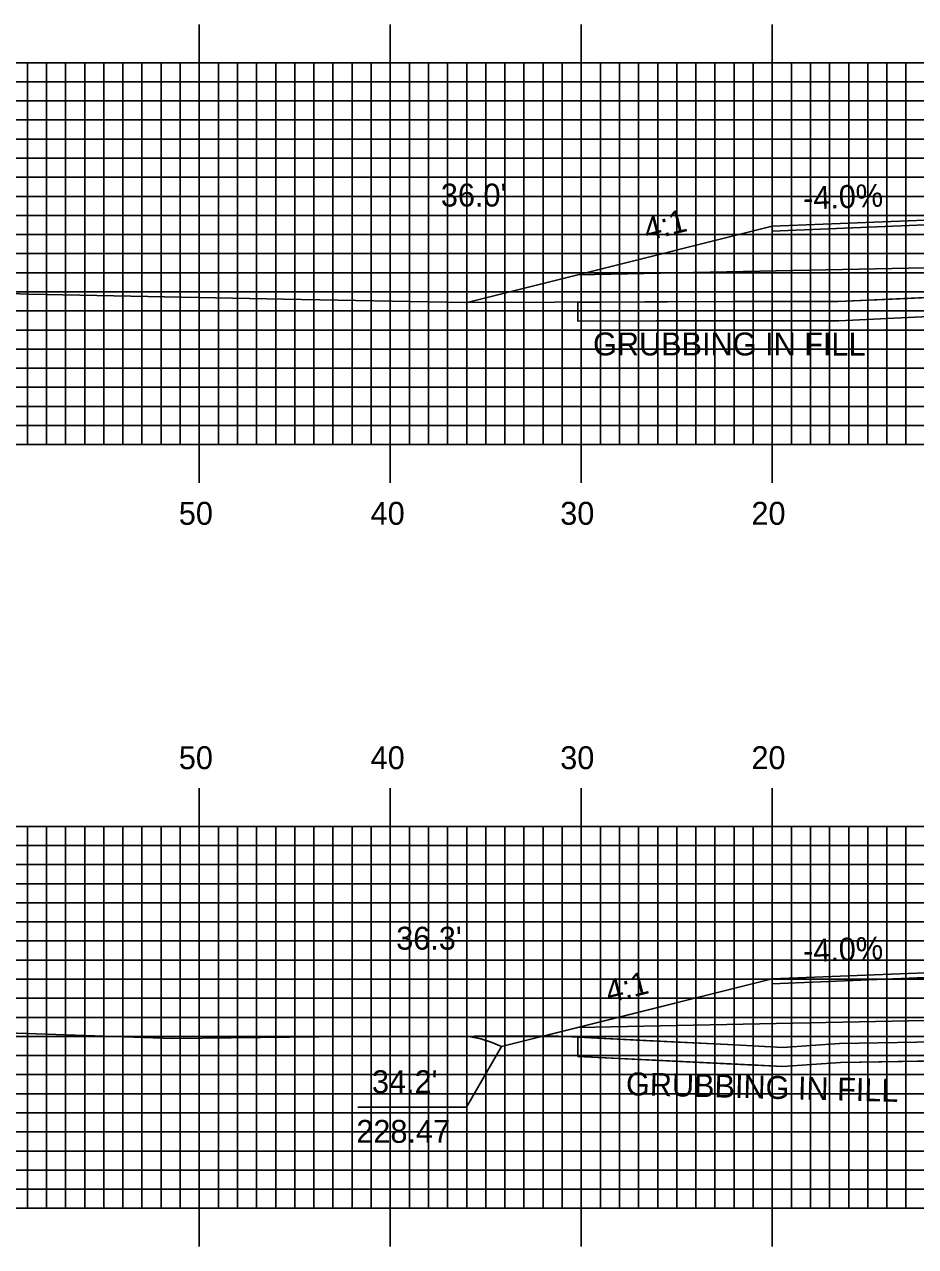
# Model space of a CAD drawing. Extents: x 1803503 to 1803847, y 442591 to 442811.
# Drawn here: x 1803610 to 1803656.6, y 442686.7 to 442750.7 of the extents above; entities that cross this region are included whole.
import ezdxf

# ---------------------------------------------------------------- set-up
doc = ezdxf.new("R2010")
doc.units = 0
for name, color, linetype in [('ANNOTATION', 7, 'Continuous'), ('D_Roadway_Centerline', 7, 'Continuous'), ('D_Roadway_Edge_Shoulder', 7, 'Continuous'), ('D_Roadway_SlopeLines', 7, 'Continuous'), ('D_Roadway_SubGrade', 7, 'Continuous'), ('D_Text_Standard', 7, 'Continuous'), ('GRUBBING IN FILL', 7, 'Continuous'), ('H_V ANNOTATION', 7, 'Continuous'), ('MAJOR', 7, 'Continuous'), ('MINOR', 7, 'Continuous'), ('S_Roadway_Centerline', 7, 'Continuous')]:
    doc.layers.add(name, color=color, linetype=linetype)

msp = doc.modelspace()

# ---------------------------------------------------------------- linework, layer by layer
at = {"layer": 'ANNOTATION'}
msp.add_lwpolyline([(1803627.447, 442693.968), (1803633.139, 442693.968), (1803634.967, 442697.135)], dxfattribs=at)
at = {"layer": 'D_Roadway_Centerline'}
for points in [[(1803633.162, 442736.104), (1803637.141, 442737.098), (1803638.967, 442737.555), (1803649.141, 442740.098), (1803657.141, 442740.418), (1803669.141, 442740.706), (1803681.141, 442740.994), (1803689.141, 442740.674), (1803699.315, 442738.131), (1803713.175, 442734.666)], [(1803632.797, 442697.673), (1803633.34, 442697.641), (1803633.882, 442697.541), (1803634.424, 442697.372), (1803634.967, 442697.135), (1803638.967, 442698.135), (1803649.141, 442700.678), (1803657.141, 442700.998), (1803669.141, 442701.286), (1803681.141, 442701.574), (1803689.141, 442701.254), (1803699.315, 442698.711), (1803706.969, 442696.797)]]:
    msp.add_lwpolyline(points, dxfattribs=at)
at = {"layer": 'D_Roadway_Edge_Shoulder'}
for points in [[(1803657.141, 442740.418), (1803649.141, 442740.098), (1803649.141, 442739.848), (1803657.141, 442740.168)], [(1803657.141, 442700.998), (1803649.141, 442700.678), (1803649.141, 442700.428), (1803657.141, 442700.748)]]:
    msp.add_lwpolyline(points, close=True, dxfattribs=at)
at = {"layer": 'D_Roadway_SlopeLines'}
for points in [[(1803649.141, 442740.098), (1803638.967, 442737.555), (1803637.141, 442737.098), (1803633.162, 442736.104)], [(1803649.141, 442700.678), (1803634.967, 442697.135)], [(1803634.967, 442697.135), (1803634.424, 442697.372), (1803633.882, 442697.541), (1803633.34, 442697.641), (1803632.797, 442697.673)]]:
    msp.add_lwpolyline(points, dxfattribs=at)
at = {"layer": 'D_Roadway_SubGrade'}
for points in [[(1803657.141, 442737.918), (1803638.967, 442737.555), (1803649.141, 442740.098), (1803649.141, 442739.848), (1803657.141, 442740.168), (1803669.141, 442740.456), (1803681.141, 442740.744), (1803689.141, 442740.424), (1803689.141, 442740.674), (1803699.315, 442738.131), (1803681.141, 442738.494), (1803669.141, 442738.206)], [(1803657.141, 442698.498), (1803638.967, 442698.135), (1803649.141, 442700.678), (1803649.141, 442700.428), (1803657.141, 442700.748), (1803669.141, 442701.036), (1803681.141, 442701.324), (1803689.141, 442701.004), (1803689.141, 442701.254), (1803699.315, 442698.711), (1803681.141, 442699.074), (1803669.141, 442698.786)]]:
    msp.add_lwpolyline(points, close=True, dxfattribs=at)
at = {"layer": 'GRUBBING IN FILL'}
for p, q in [((1803638.967, 442736.125), (1803638.967, 442735.125)), ((1803638.967, 442736.125), (1803638.967, 442735.125)), ((1803638.967, 442697.625), (1803638.967, 442696.624)), ((1803638.967, 442697.625), (1803638.967, 442696.624))]:
    msp.add_line(p, q, dxfattribs=at)
for points in [[(1803638.967, 442736.125), (1803640.1, 442736.129), (1803647.171, 442736.154), (1803649.883, 442736.153), (1803652.596, 442736.152), (1803656.22, 442736.322), (1803659.844, 442736.493), (1803662, 442736.585), (1803664.222, 442736.368), (1803667.485, 442736.044), (1803668.526, 442735.936), (1803669.141, 442735.915), (1803669.141, 442734.915), (1803668.457, 442734.938), (1803667.401, 442735.047), (1803664.176, 442735.368), (1803662.007, 442735.579), (1803659.886, 442735.494), (1803656.253, 442735.323), (1803652.62, 442735.152), (1803649.896, 442735.153), (1803647.172, 442735.154), (1803643.069, 442735.139), (1803638.967, 442735.125)], [(1803638.967, 442736.125), (1803640.1, 442736.129), (1803647.171, 442736.154), (1803649.883, 442736.153), (1803652.596, 442736.152), (1803656.22, 442736.322), (1803659.844, 442736.493), (1803662, 442736.585), (1803664.222, 442736.368), (1803667.485, 442736.044), (1803668.526, 442735.936), (1803669.141, 442735.915), (1803669.141, 442734.915), (1803668.457, 442734.938), (1803667.401, 442735.047), (1803664.176, 442735.368), (1803662.007, 442735.579), (1803659.886, 442735.494), (1803656.253, 442735.323), (1803652.62, 442735.152), (1803649.896, 442735.153), (1803647.172, 442735.154), (1803643.069, 442735.139), (1803638.967, 442735.125)], [(1803638.967, 442697.625), (1803642.38, 442697.456), (1803647.158, 442697.219), (1803648.422, 442697.153), (1803649.687, 442697.087), (1803651.177, 442697.19), (1803652.667, 442697.293), (1803659.74, 442697.415), (1803666.814, 442697.536), (1803669.141, 442697.425), (1803669.141, 442696.424), (1803666.798, 442696.536), (1803659.754, 442696.415), (1803652.71, 442696.294), (1803651.203, 442696.189), (1803649.695, 442696.085), (1803648.401, 442696.153), (1803643.037, 442696.422), (1803638.967, 442696.624)], [(1803638.967, 442697.625), (1803642.38, 442697.456), (1803647.158, 442697.219), (1803648.422, 442697.153), (1803649.687, 442697.087), (1803651.177, 442697.19), (1803652.667, 442697.293), (1803659.74, 442697.415), (1803666.814, 442697.536), (1803669.141, 442697.425), (1803669.141, 442696.424), (1803666.798, 442696.536), (1803659.754, 442696.415), (1803652.71, 442696.294), (1803651.203, 442696.189), (1803649.695, 442696.085), (1803648.401, 442696.153), (1803643.037, 442696.422), (1803638.967, 442696.624)]]:
    msp.add_lwpolyline(points, close=True, dxfattribs=at)
for points in [[(1803638.967, 442735.125), (1803647.172, 442735.154), (1803652.62, 442735.152), (1803659.886, 442735.494), (1803661.922, 442735.57), (1803662.007, 442735.579), (1803666.345, 442735.157), (1803668.457, 442734.938), (1803669.539, 442734.901), (1803680.472, 442734.876), (1803689.308, 442734.416), (1803694.454, 442734.291), (1803699.315, 442734.13)], [(1803638.967, 442735.125), (1803647.172, 442735.154), (1803652.62, 442735.152), (1803659.886, 442735.494), (1803661.922, 442735.57), (1803662.007, 442735.579), (1803666.345, 442735.157), (1803668.457, 442734.938), (1803669.539, 442734.901), (1803680.472, 442734.876), (1803689.308, 442734.416), (1803694.454, 442734.291), (1803699.315, 442734.13)], [(1803638.967, 442696.624), (1803647.107, 442696.22), (1803649.695, 442696.085), (1803652.71, 442696.294), (1803666.798, 442696.536), (1803670.752, 442696.347), (1803672.896, 442696.306), (1803676.279, 442696.343), (1803678.656, 442696.329), (1803680.162, 442696.198), (1803689.753, 442695.875), (1803696.384, 442695.764), (1803699.315, 442695.812)], [(1803638.967, 442696.624), (1803647.107, 442696.22), (1803649.695, 442696.085), (1803652.71, 442696.294), (1803666.798, 442696.536), (1803670.752, 442696.347), (1803672.896, 442696.306), (1803676.279, 442696.343), (1803678.656, 442696.329), (1803680.162, 442696.198), (1803689.753, 442695.875), (1803696.384, 442695.764), (1803699.315, 442695.812)]]:
    msp.add_lwpolyline(points, dxfattribs=at)
at = {"layer": 'MAJOR'}
for p, q in [((1803619.141, 442750.669), (1803619.141, 442748.665)), ((1803629.141, 442750.669), (1803629.141, 442748.665)), ((1803639.141, 442750.669), (1803639.141, 442748.665)), ((1803649.141, 442750.669), (1803649.141, 442748.665)), ((1803529.141, 442748.665), (1803809.141, 442748.665)), ((1803529.141, 442748.665), (1803809.141, 442748.665)), ((1803619.141, 442728.665), (1803619.141, 442748.665)), ((1803629.141, 442728.665), (1803629.141, 442748.665)), ((1803639.141, 442728.665), (1803639.141, 442748.665)), ((1803649.141, 442728.665), (1803649.141, 442748.665)), ((1803529.141, 442743.665), (1803809.141, 442743.665)), ((1803529.141, 442738.665), (1803809.141, 442738.665)), ((1803529.141, 442733.665), (1803809.141, 442733.665)), ((1803529.141, 442728.665), (1803809.141, 442728.665)), ((1803529.141, 442728.665), (1803809.141, 442728.665)), ((1803619.141, 442726.661), (1803619.141, 442728.665)), ((1803629.141, 442726.661), (1803629.141, 442728.665)), ((1803639.141, 442726.661), (1803639.141, 442728.665)), ((1803649.141, 442726.661), (1803649.141, 442728.665)), ((1803619.141, 442710.669), (1803619.141, 442708.665)), ((1803629.141, 442710.669), (1803629.141, 442708.665)), ((1803639.141, 442710.669), (1803639.141, 442708.665)), ((1803649.141, 442710.669), (1803649.141, 442708.665)), ((1803529.141, 442708.665), (1803809.141, 442708.665)), ((1803529.141, 442708.665), (1803809.141, 442708.665)), ((1803619.141, 442688.665), (1803619.141, 442708.665)), ((1803629.141, 442688.665), (1803629.141, 442708.665)), ((1803639.141, 442688.665), (1803639.141, 442708.665)), ((1803649.141, 442688.665), (1803649.141, 442708.665)), ((1803529.141, 442703.665), (1803809.141, 442703.665)), ((1803529.141, 442698.665), (1803809.141, 442698.665)), ((1803529.141, 442693.665), (1803809.141, 442693.665)), ((1803529.141, 442688.665), (1803809.141, 442688.665)), ((1803529.141, 442688.665), (1803809.141, 442688.665)), ((1803619.141, 442686.661), (1803619.141, 442688.665)), ((1803629.141, 442686.661), (1803629.141, 442688.665)), ((1803639.141, 442686.661), (1803639.141, 442688.665)), ((1803649.141, 442686.661), (1803649.141, 442688.665))]:
    msp.add_line(p, q, dxfattribs=at)
at = {"layer": 'MINOR'}
for p, q in [((1803610.141, 442728.665), (1803610.141, 442748.665)), ((1803611.141, 442728.665), (1803611.141, 442748.665)), ((1803612.141, 442728.665), (1803612.141, 442748.665)), ((1803613.141, 442728.665), (1803613.141, 442748.665)), ((1803614.141, 442728.665), (1803614.141, 442748.665)), ((1803615.141, 442728.665), (1803615.141, 442748.665)), ((1803616.141, 442728.665), (1803616.141, 442748.665)), ((1803617.141, 442728.665), (1803617.141, 442748.665)), ((1803618.141, 442728.665), (1803618.141, 442748.665)), ((1803620.141, 442728.665), (1803620.141, 442748.665)), ((1803621.141, 442728.665), (1803621.141, 442748.665)), ((1803622.141, 442728.665), (1803622.141, 442748.665)), ((1803623.141, 442728.665), (1803623.141, 442748.665)), ((1803624.141, 442728.665), (1803624.141, 442748.665)), ((1803625.141, 442728.665), (1803625.141, 442748.665)), ((1803626.141, 442728.665), (1803626.141, 442748.665)), ((1803627.141, 442728.665), (1803627.141, 442748.665)), ((1803628.141, 442728.665), (1803628.141, 442748.665)), ((1803630.141, 442728.665), (1803630.141, 442748.665)), ((1803631.141, 442728.665), (1803631.141, 442748.665)), ((1803632.141, 442728.665), (1803632.141, 442748.665)), ((1803633.141, 442728.665), (1803633.141, 442748.665)), ((1803634.141, 442728.665), (1803634.141, 442748.665)), ((1803635.141, 442728.665), (1803635.141, 442748.665)), ((1803636.141, 442728.665), (1803636.141, 442748.665)), ((1803637.141, 442728.665), (1803637.141, 442748.665)), ((1803638.141, 442728.665), (1803638.141, 442748.665)), ((1803640.141, 442728.665), (1803640.141, 442748.665)), ((1803641.141, 442728.665), (1803641.141, 442748.665)), ((1803642.141, 442728.665), (1803642.141, 442748.665)), ((1803643.141, 442728.665), (1803643.141, 442748.665)), ((1803644.141, 442728.665), (1803644.141, 442748.665)), ((1803645.141, 442728.665), (1803645.141, 442748.665)), ((1803646.141, 442728.665), (1803646.141, 442748.665)), ((1803647.141, 442728.665), (1803647.141, 442748.665)), ((1803648.141, 442728.665), (1803648.141, 442748.665)), ((1803650.141, 442728.665), (1803650.141, 442748.665)), ((1803651.141, 442728.665), (1803651.141, 442748.665)), ((1803652.141, 442728.665), (1803652.141, 442748.665)), ((1803653.141, 442728.665), (1803653.141, 442748.665)), ((1803654.141, 442728.665), (1803654.141, 442748.665)), ((1803655.141, 442728.665), (1803655.141, 442748.665)), ((1803656.141, 442728.665), (1803656.141, 442748.665)), ((1803529.141, 442747.665), (1803809.141, 442747.665)), ((1803529.141, 442746.665), (1803809.141, 442746.665)), ((1803529.141, 442745.665), (1803809.141, 442745.665)), ((1803529.141, 442744.665), (1803809.141, 442744.665)), ((1803529.141, 442742.665), (1803809.141, 442742.665)), ((1803529.141, 442741.665), (1803809.141, 442741.665)), ((1803529.141, 442740.665), (1803809.141, 442740.665)), ((1803529.141, 442739.665), (1803809.141, 442739.665)), ((1803529.141, 442737.665), (1803809.141, 442737.665)), ((1803529.141, 442736.665), (1803809.141, 442736.665)), ((1803529.141, 442735.665), (1803809.141, 442735.665)), ((1803529.141, 442734.665), (1803809.141, 442734.665)), ((1803529.141, 442732.665), (1803809.141, 442732.665)), ((1803529.141, 442731.665), (1803809.141, 442731.665)), ((1803529.141, 442730.665), (1803809.141, 442730.665)), ((1803529.141, 442729.665), (1803809.141, 442729.665)), ((1803610.141, 442688.665), (1803610.141, 442708.665)), ((1803611.141, 442688.665), (1803611.141, 442708.665)), ((1803612.141, 442688.665), (1803612.141, 442708.665)), ((1803613.141, 442688.665), (1803613.141, 442708.665)), ((1803614.141, 442688.665), (1803614.141, 442708.665)), ((1803615.141, 442688.665), (1803615.141, 442708.665)), ((1803616.141, 442688.665), (1803616.141, 442708.665)), ((1803617.141, 442688.665), (1803617.141, 442708.665)), ((1803618.141, 442688.665), (1803618.141, 442708.665)), ((1803620.141, 442688.665), (1803620.141, 442708.665)), ((1803621.141, 442688.665), (1803621.141, 442708.665)), ((1803622.141, 442688.665), (1803622.141, 442708.665)), ((1803623.141, 442688.665), (1803623.141, 442708.665)), ((1803624.141, 442688.665), (1803624.141, 442708.665)), ((1803625.141, 442688.665), (1803625.141, 442708.665)), ((1803626.141, 442688.665), (1803626.141, 442708.665)), ((1803627.141, 442688.665), (1803627.141, 442708.665)), ((1803628.141, 442688.665), (1803628.141, 442708.665)), ((1803630.141, 442688.665), (1803630.141, 442708.665)), ((1803631.141, 442688.665), (1803631.141, 442708.665)), ((1803632.141, 442688.665), (1803632.141, 442708.665)), ((1803633.141, 442688.665), (1803633.141, 442708.665)), ((1803634.141, 442688.665), (1803634.141, 442708.665)), ((1803635.141, 442688.665), (1803635.141, 442708.665)), ((1803636.141, 442688.665), (1803636.141, 442708.665)), ((1803637.141, 442688.665), (1803637.141, 442708.665)), ((1803638.141, 442688.665), (1803638.141, 442708.665)), ((1803640.141, 442688.665), (1803640.141, 442708.665)), ((1803641.141, 442688.665), (1803641.141, 442708.665)), ((1803642.141, 442688.665), (1803642.141, 442708.665)), ((1803643.141, 442688.665), (1803643.141, 442708.665)), ((1803644.141, 442688.665), (1803644.141, 442708.665)), ((1803645.141, 442688.665), (1803645.141, 442708.665)), ((1803646.141, 442688.665), (1803646.141, 442708.665)), ((1803647.141, 442688.665), (1803647.141, 442708.665)), ((1803648.141, 442688.665), (1803648.141, 442708.665)), ((1803650.141, 442688.665), (1803650.141, 442708.665)), ((1803651.141, 442688.665), (1803651.141, 442708.665)), ((1803652.141, 442688.665), (1803652.141, 442708.665)), ((1803653.141, 442688.665), (1803653.141, 442708.665)), ((1803654.141, 442688.665), (1803654.141, 442708.665)), ((1803655.141, 442688.665), (1803655.141, 442708.665)), ((1803656.141, 442688.665), (1803656.141, 442708.665)), ((1803529.141, 442707.665), (1803809.141, 442707.665)), ((1803529.141, 442706.665), (1803809.141, 442706.665)), ((1803529.141, 442705.665), (1803809.141, 442705.665)), ((1803529.141, 442704.665), (1803809.141, 442704.665)), ((1803529.141, 442702.665), (1803809.141, 442702.665)), ((1803529.141, 442701.665), (1803809.141, 442701.665)), ((1803529.141, 442700.665), (1803809.141, 442700.665)), ((1803529.141, 442699.665), (1803809.141, 442699.665)), ((1803529.141, 442697.665), (1803809.141, 442697.665)), ((1803529.141, 442696.665), (1803809.141, 442696.665)), ((1803529.141, 442695.665), (1803809.141, 442695.665)), ((1803529.141, 442694.665), (1803809.141, 442694.665)), ((1803529.141, 442692.665), (1803809.141, 442692.665)), ((1803529.141, 442691.665), (1803809.141, 442691.665)), ((1803529.141, 442690.665), (1803809.141, 442690.665)), ((1803529.141, 442689.665), (1803809.141, 442689.665))]:
    msp.add_line(p, q, dxfattribs=at)
at = {"layer": 'S_Roadway_Centerline'}
for points in [[(1803602.328, 442736.835), (1803610.211, 442736.538), (1803623.544, 442736.276), (1803633.029, 442736.103), (1803647.171, 442736.154), (1803652.596, 442736.152), (1803659.844, 442736.493), (1803661.848, 442736.568), (1803662, 442736.585), (1803666.445, 442736.152), (1803668.526, 442735.936), (1803669.557, 442735.901), (1803680.499, 442735.876), (1803689.346, 442735.416), (1803694.483, 442735.291), (1803711.435, 442734.727), (1803719.653, 442734.436)], [(1803603.953, 442698.023), (1803617.751, 442697.563), (1803625.398, 442697.642), (1803637.603, 442697.693), (1803647.158, 442697.219), (1803649.687, 442697.087), (1803652.667, 442697.293), (1803666.814, 442697.536), (1803670.785, 442697.346), (1803672.9, 442697.306), (1803676.277, 442697.344), (1803678.703, 442697.329), (1803680.222, 442697.196), (1803689.778, 442696.875), (1803696.384, 442696.765), (1803703.887, 442696.887), (1803710.51, 442696.694), (1803718.608, 442696.121)]]:
    msp.add_lwpolyline(points, dxfattribs=at)

# ---------------------------------------------------------------- texts
at = {"layer": 'ANNOTATION'}
for s, rotation, p in [('-4.0%', 2.29061, (1803650.773, 442740.965)), ('4:1', 14.03624, (1803642.59, 442739.322)), ('-4.0%', 2.29061, (1803650.773, 442701.545)), ('4:1', 14.03624, (1803640.59, 442699.402))]:
    msp.add_text(s, height=1.2, rotation=rotation, dxfattribs=at).set_placement(p)
for s, p in [("34.2'", (1803628.182, 442694.694)), ('228.47', (1803627.363, 442692.094))]:
    msp.add_text(s, height=1.2, dxfattribs=at).set_placement(p)
at = {"layer": 'D_Text_Standard'}
for s, p in [("36.0'", (1803631.789, 442741.132)), ("36.3'", (1803629.451, 442702.211))]:
    msp.add_text(s, height=1.2, dxfattribs=at).set_placement(p)
at = {"layer": 'GRUBBING IN FILL'}
for rotation, p in [(359.97745, (1803639.756, 442733.335)), (358.55884, (1803641.468, 442694.594))]:
    msp.add_text('GRUBBING IN FILL', height=1.2, rotation=rotation, dxfattribs=at).set_placement(p)
at = {"layer": 'H_V ANNOTATION'}
for s, p in [('50', (1803618.07, 442724.465)), ('40', (1803628.113, 442724.465)), ('30', (1803638.038, 442724.465)), ('20', (1803648.049, 442724.465)), ('50', (1803618.07, 442711.665)), ('40', (1803628.113, 442711.665)), ('30', (1803638.038, 442711.665)), ('20', (1803648.049, 442711.665))]:
    msp.add_text(s, height=1.2, dxfattribs=at).set_placement(p)

doc.saveas('drawing.dxf')
